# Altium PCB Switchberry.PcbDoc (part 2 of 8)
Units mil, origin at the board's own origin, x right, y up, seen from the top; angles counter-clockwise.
Board outline 4500 x 3824.8 mil, 6 copper layers (L01-TOP, L02-GND, L03-SIG, L04-SIG, L05-GND, L06-BOT), stack 49.214 mil thick; 431 components, 322 nets, 1699 pads, 1274 vias.
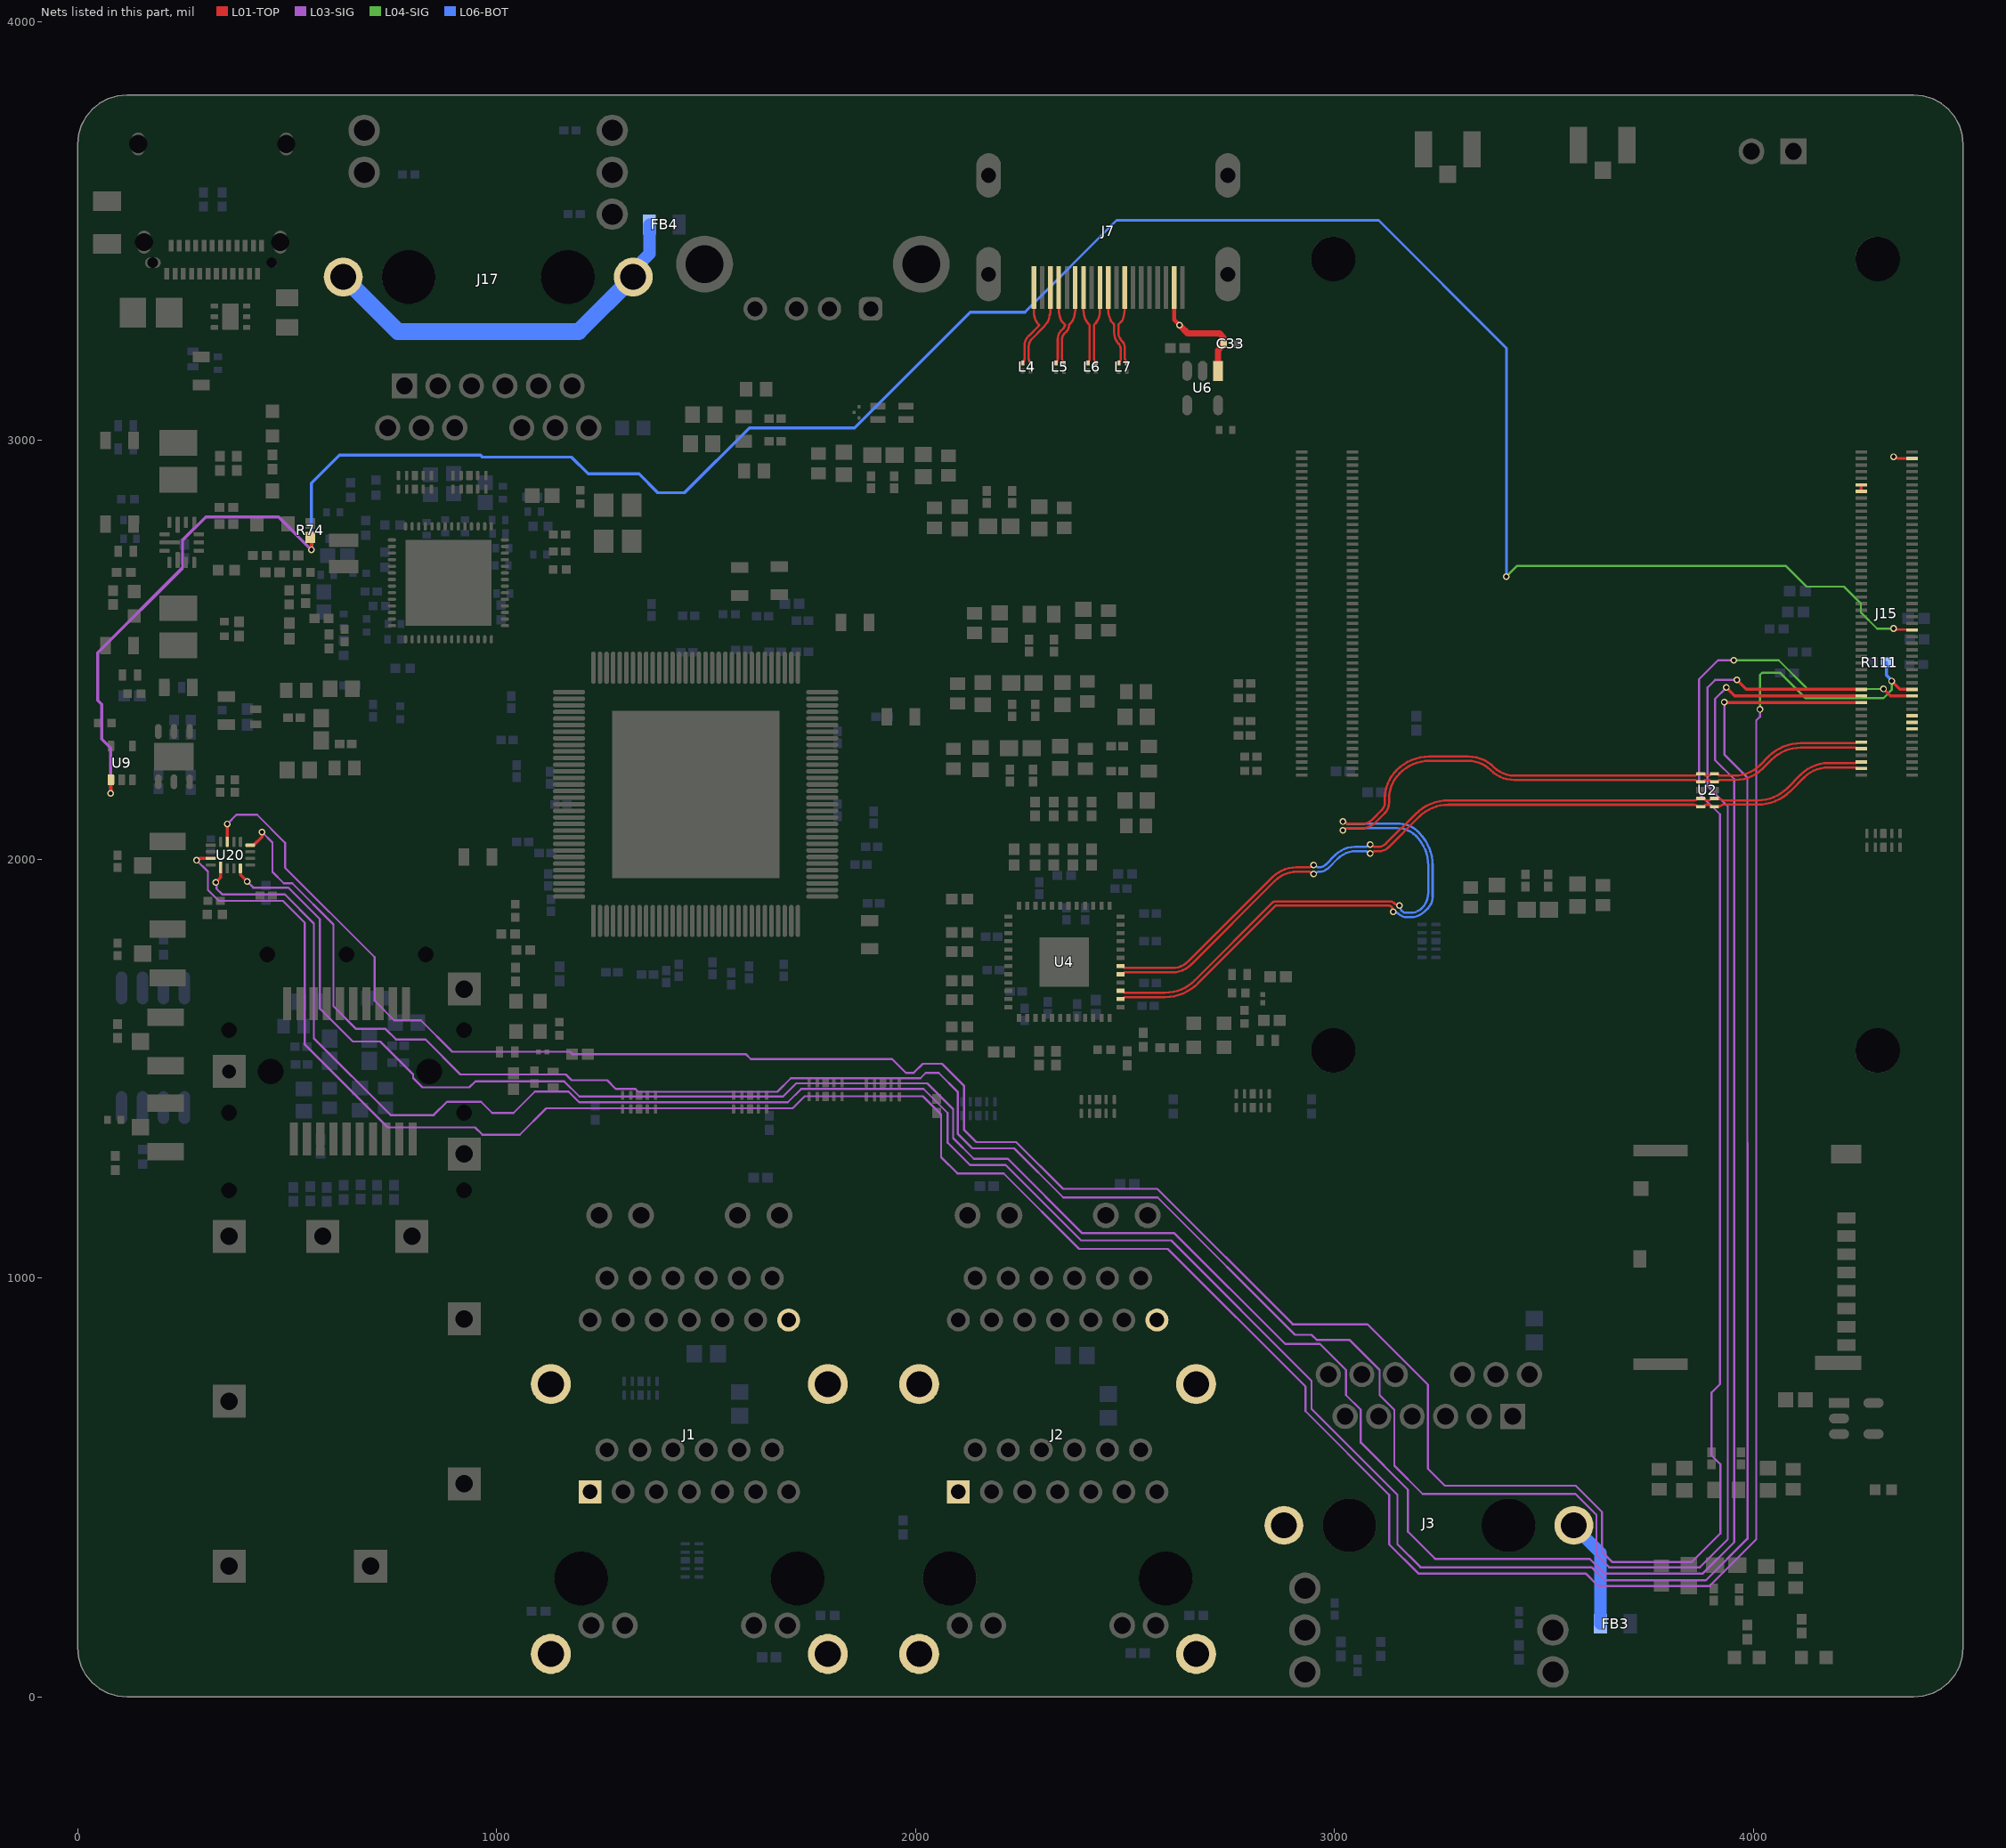
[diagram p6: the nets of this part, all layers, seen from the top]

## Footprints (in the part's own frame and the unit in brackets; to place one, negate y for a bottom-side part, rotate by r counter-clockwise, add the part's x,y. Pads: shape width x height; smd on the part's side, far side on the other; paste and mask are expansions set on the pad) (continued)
FP-CRCW0402-e3-IPC_B [mil]
  rect 22.37x22.54 smd paste+0 mask+0: 1(-17.8,0) 2(17.8,0)
  silkscreen extent -29,-27 29,27, body extent -35,-17 35,17, height 10
FP-CRCW0402-e3-IPC_C [mil]
  rect 18.43x18.6 smd paste+0 mask+0: 1(-15.83,0) 2(15.83,0)
  silkscreen extent -25,-27 25,27, body extent -20,-10 20,10, height 16
FP-DF40HC_3_0_-100DS-0_4V-MFG [mm]
  rect 0.2x0.7 smd paste-1000 mask+0: 1(-9.8,-1.54) 2(-9.8,1.54) 3(-9.4,-1.54) 4(-9.4,1.54) 5(-9,-1.54) 6(-9,1.54) 7(-8.6,-1.54) 8(-8.6,1.54) 9(-8.2,-1.54) 10(-8.2,1.54) 11(-7.8,-1.54) 12(-7.8,1.54) 13(-7.4,-1.54) 14(-7.4,1.54) 15(-7,-1.54) 16(-7,1.54) 17(-6.6,-1.54) 18(-6.6,1.54) 19(-6.2,-1.54) 20(-6.2,1.54) 21(-5.8,-1.54) 22(-5.8,1.54) 23(-5.4,-1.54) 24(-5.4,1.54) 25(-5,-1.54) 26(-5,1.54) 27(-4.6,-1.54) 28(-4.6,1.54) 29(-4.2,-1.54) 30(-4.2,1.54) 31(-3.8,-1.54) 32(-3.8,1.54) 33(-3.4,-1.54) 34(-3.4,1.54) 35(-3,-1.54) 36(-3,1.54) 37(-2.6,-1.54) 38(-2.6,1.54) 39(-2.2,-1.54) 40(-2.2,1.54) 41(-1.8,-1.54) 42(-1.8,1.54) 43(-1.4,-1.54) 44(-1.4,1.54) 45(-1,-1.54) 46(-1,1.54) 47(-0.6,-1.54) 48(-0.6,1.54) 49(-0.2,-1.54) 50(-0.2,1.54) 51(0.2,-1.54) 52(0.2,1.54) 53(0.6,-1.54) 54(0.6,1.54) 55(1,-1.54) 56(1,1.54) 57(1.4,-1.54) 58(1.4,1.54) 59(1.8,-1.54) 60(1.8,1.54) 61(2.2,-1.54) 62(2.2,1.54) 63(2.6,-1.54) 64(2.6,1.54) 65(3,-1.54) 66(3,1.54) 67(3.4,-1.54) 68(3.4,1.54) 69(3.8,-1.54) 70(3.8,1.54) 71(4.2,-1.54) 72(4.2,1.54) 73(4.6,-1.54) 74(4.6,1.54) 75(5,-1.54) 76(5,1.54) 77(5.4,-1.54) 78(5.4,1.54) 79(5.8,-1.54) 80(5.8,1.54) 81(6.2,-1.54) 82(6.2,1.54) 83(6.6,-1.54) 84(6.6,1.54) 85(7,-1.54) 86(7,1.54) 87(7.4,-1.54) 88(7.4,1.54) 89(7.8,-1.54) 90(7.8,1.54) 91(8.2,-1.54) 92(8.2,1.54) 93(8.6,-1.54) 94(8.6,1.54) 95(9,-1.54) 96(9,1.54) 97(9.4,-1.54) 98(9.4,1.54) 99(9.8,-1.54) 100(9.8,1.54)
  silkscreen extent -11.4,-2.62 11.4,1.57, body extent -11.5,-1.99 11.5,1.99, height 0.25
FP-DFE252012C-IPC_A [mil]
  rect 61.22x90.8 smd paste+0 mask+0: 1(-44.32,0) 2(44.32,0)
  silkscreen extent -75,-61 75,61, body extent -95,-65 95,65, height 10
FP-DLM0Q-MFG [mm]
  rect 0.3x0.23 smd paste+0 mask+0: 1(-0.25,0.24) 2(0.25,0.24) 3(0.25,-0.24) 4(-0.25,-0.24)
  silkscreen extent -1.1,-0.73 0.28,0.73, body extent -0.5,-0.46 0.5,0.46, height 0.25
FP-DLW21S-MFG [mm]
  rect 0.9x0.4 smd paste+0 mask+0: 1(-0.85,-0.4) 2(0.85,-0.4) 3(0.85,0.4) 4(-0.85,0.4)
  silkscreen extent -1.97,-1.01 1.11,1, body extent -1.4,-0.8 1.4,0.8, height 0.25
FP-DMX0003A-MFG [mm]
  rrect50% 0.2x0.2 smd paste-1000 mask-1000: 1(-0.15,0) 2(0.15,-0.34) 3(0.15,0.34)
  silkscreen extent -0.35,-0.87 0.35,0.87, body extent -0.45,-0.65 0.45,0.65, height 0.25
FP-DQA0010A-MFG [mm]
  rrect50% 0.565x0.2 smd paste+0 mask+0: 1(-0.417,1) 2(-0.417,0.5) 4(-0.417,-0.5) 5(-0.417,-1) 6(0.417,-1) 7(0.417,-0.5) 9(0.417,0.5) 10(0.417,1)
  rrect25% 0.565x0.4 smd paste-1000 mask+0: 3(-0.417,0) 8(0.417,0)
  silkscreen extent -1.37,-1.48 0.55,1.48, body extent -0.8,-1.4 0.8,1.4, height 0.25
FP-DRV0006A-MFG [mm]
  rrect33% 0.45x0.3 smd paste+0 mask+0: 1(-0.975,0.65) 2(-0.975,0) 3(-0.975,-0.65) 4(0.975,-0.65) 5(0.975,0) 6(0.975,0.65)
  rrect10% 1x1.6 smd paste-1000 mask+0: 7(0,0)
  silkscreen extent -1.88,-1.17 1.05,1.17, body extent -1.3,-1.15 1.3,1.15, height 0.25
FP-ECS-TXO-2520-MFG [mm]
  rect 0.9x0.8 smd paste+0 mask+0: 1(-0.925,-0.725) 2(0.925,-0.725) 3(0.925,0.725) 4(-0.925,0.725)
  silkscreen extent -1.05,-1.8 0.1,1.05, body extent -1.48,-1.22 1.48,1.22, height 0.25
FP-GRM15-MFG [mm]
  rect 0.4x0.5 smd paste+0 mask+0: 1(-0.4,0) 2(0.4,0)
  silkscreen extent -0.53,-0.63 0.53,0.63, body extent -0.3,-0.16 0.3,0.16, height 0.33
FP-GRM188-0_2-IPC_C [mil]
  rect 35.63x35.68 smd paste+0 mask+0: 1(-23.64,0) 2(23.64,0)
  silkscreen extent -41,-35 41,35, body extent -45,-24 45,24, height 10
FP-LTST-C190GKT-MFG [mm]
  rect 0.8x0.8 smd paste+0 mask+0: 1(-0.75,0) 2(0.75,0)
  silkscreen extent -1.92,-0.85 0.85,0.85, body extent -1.25,-0.55 1.25,0.55, height 0.25
FP-M20-9990246-MFG [mm]
  rect 1.57x1.57 hole 1.02 paste-2539.97 mask+0: 1(-1.27,0)
  round 1.57 hole 1.02 paste-2539.97 mask+0: 2(1.27,0)
  silkscreen extent -3.55,-1.32 2.79,1.32, body extent -2.89,-1.42 2.89,1.42, height 0.25
FP-RQR0014A-MFG [mm]
  rrect40% 0.625x0.25 smd paste+0 mask+0: 1(-1.038,0.5) 2(-1.038,0) 3(-1.038,-0.5) 8(1.038,-0.5) 10(1.038,0.5)
  rrect40% 0.25x0.675 smd paste+0 mask+0: 4(-0.75,-1.212) 5(-0.25,-1.212) 7(0.75,-1.212) 11(0.75,1.212) 13(-0.25,1.212) 14(-0.75,1.212)
  rrect40% 0.25x0.975 smd paste+0 mask+0: 6(0.25,-1.062) 12(0.25,1.062)
  rrect40% 1.225x0.25 smd paste+0 mask+0: 9(0.737,0)
  silkscreen extent -2.02,-1.55 1.35,1.55, body extent -1.45,-1.65 1.45,1.65, height 0.25
FP-RSV0016A-MFG [mm]
  rrect50% 0.7x0.2 smd paste+0 mask+0: 1(-0.75,0.6)
  rrect50% 0.6x0.2 smd paste+0 mask+0: 2(-0.8,0.2) 3(-0.8,-0.2) 4(-0.8,-0.6) 9(0.8,-0.6) 10(0.8,-0.2) 11(0.8,0.2) 12(0.8,0.6)
  rrect50% 0.2x0.6 smd paste+0 mask+0: 5(-0.6,-1.2) 6(-0.2,-1.2) 7(0.2,-1.2) 8(0.6,-1.2) 13(0.6,1.2) 14(0.2,1.2) 15(-0.2,1.2) 16(-0.6,1.2)
  silkscreen extent -1.9,-1.68 1.28,1.68, body extent -1.2,-1.6 1.2,1.6, height 0.25
FP-RT9742GGJ5-IPC_C [mil]
  rect 48.02x23.17 smd paste+0 mask+0: 1(-41.07,36.99)
  rrect100% 48.02x23.17 smd paste+0 mask+0: 2(-41.07,0) 3(-41.07,-36.99) 4(41.07,-36.99) 5(41.07,36.99)
  silkscreen extent -90,-57 3,57, body extent -69,-61 69,61, height 10
FP-SOT23_Standard-MFG [mm]
  rect 0.9x0.8 smd paste+0 mask+0: 1(-1,0.95) 2(-1,-0.95) 3(1,0)
  silkscreen extent -0.18,-1.5 0.7,1.5, body extent -1.55,-1.6 1.55,1.6, height 0.25
FP-U_FL-R-SMT-1_10-MFG [mm]
  rect 1x1.05 smd paste-1000 mask+0: 1(0,1.525)
  rect 1.05x2.2 smd paste-1000 mask+0: 2(-1.475,0) 3(1.475,0)
  silkscreen extent -0.58,-1.38 0.58,-1.38, body extent -2.1,-1.48 2.1,2.15, height 0.25
"I225 QFN56" [mm]
  oval 0.5x0.2 smd: 1(-3.425,2.6) 2(-3.425,2.2) 3(-3.425,1.8) 4(-3.425,1.4) 5(-3.425,1) 6(-3.425,0.6) 7(-3.425,0.2) 8(-3.425,-0.2) 9(-3.425,-0.6) 10(-3.425,-1) 11(-3.425,-1.4) 12(-3.425,-1.8) 13(-3.425,-2.2) 14(-3.425,-2.6) 29(3.425,-2.6) 30(3.425,-2.2) 31(3.425,-1.8) 32(3.425,-1.4) 33(3.425,-1) 34(3.425,-0.6) 35(3.425,-0.2) 36(3.425,0.2) 37(3.425,0.6) 38(3.425,1) 39(3.425,1.4) 40(3.425,1.8) 41(3.425,2.2) 42(3.425,2.6)
  oval 0.2x0.5 smd: 15(-2.6,-3.425) 16(-2.2,-3.425) 17(-1.8,-3.425) 18(-1.4,-3.425) 19(-1,-3.425) 20(-0.6,-3.425) 21(-0.2,-3.425) 22(0.2,-3.425) 23(0.6,-3.425) 24(1,-3.425) 25(1.4,-3.425) 26(1.8,-3.425) 27(2.2,-3.425) 28(2.6,-3.425) 43(2.6,3.425) 44(2.2,3.425) 45(1.8,3.425) 46(1.4,3.425) 47(1,3.425) 48(0.6,3.425) 49(0.2,3.425) 50(-0.2,3.425) 51(-0.6,3.425) 52(-1,3.425) 53(-1.4,3.425) 54(-1.8,3.425) 55(-2.2,3.425) 56(-2.6,3.425)
  rect 5.2x5.2 smd: PAD(0,0)
  silkscreen extent -4.42,-3.65 3.65,3.65, body extent -3.5,-3.5 3.5,3.5, height 0.9
MCHP-SOIC-S2A8_M [mm] "SOIC, 8-Leads, Body 5.275x5.275mm, Pitch 1.27mm, IPC Low Density"
  oval 2x0.7 smd: 1(-3.625,1.905) 2(-3.625,0.635) 3(-3.625,-0.635) 4(-3.625,-1.905) 5(3.625,-1.905) 6(3.625,-0.635) 7(3.625,0.635) 8(3.625,1.905)
  silkscreen extent -3.75,-2.7 2.23,2.93, body extent -2.7,-2.7 2.7,2.7, height 2.16
MICL-QFN-48_V [mm] "QFN, 48-Leads, Body 7.05x7.05mm, Pitch 0.5mm"
  rect 0.5x0.25 smd: 1(-3.4,2.75) 2(-3.4,2.25) 3(-3.4,1.75) 4(-3.4,1.25) 5(-3.4,0.75) 6(-3.4,0.25) 7(-3.4,-0.25) 8(-3.4,-0.75) 9(-3.4,-1.25) 10(-3.4,-1.75) 11(-3.4,-2.25) 12(-3.4,-2.75) 25(3.4,-2.75) 26(3.4,-2.25) 27(3.4,-1.75) 28(3.4,-1.25) 29(3.4,-0.75) 30(3.4,-0.25) 31(3.4,0.25) 32(3.4,0.75) 33(3.4,1.25) 34(3.4,1.75) 35(3.4,2.25) 36(3.4,2.75)
  rect 0.25x0.5 smd: 13(-2.75,-3.4) 14(-2.25,-3.4) 15(-1.75,-3.4) 16(-1.25,-3.4) 17(-0.75,-3.4) 18(-0.25,-3.4) 19(0.25,-3.4) 20(0.75,-3.4) 21(1.25,-3.4) 22(1.75,-3.4) 23(2.25,-3.4) 24(2.75,-3.4) 37(2.75,3.4) 38(2.25,3.4) 39(1.75,3.4) 40(1.25,3.4) 41(0.75,3.4) 42(0.25,3.4) 43(-0.25,3.4) 44(-0.75,3.4) 45(-1.25,3.4) 46(-1.75,3.4) 47(-2.25,3.4) 48(-2.75,3.4)
  rect 3x3 smd paste-4: 49(0,0)
  silkscreen extent -4.33,2.63 -4.08,2.87, body extent -3.5,-3.5 3.5,3.5, height 0.9
MOLX-74754-0101_V [mm] "SFP+ Cage, 1-Port, Body 49x15.9mm"
  rect 2x2 hole 1.05: MH1(-7.125,13.55) MH2(-7.125,3.55) MH3(-7.125,-6.45) MH4(-7.125,-16.45) MH6(7.125,-1.45) MH7(7.125,8.55) MH8(7.125,18.55) MH9(-1.455,18.55) MH10(-3.955,-1.45) MH11(1.445,-1.45)
  rect 2x2 hole 0.85: MH5(7.125,-11.45)
  round 0 hole 0.95: MH12(-7.13,-4.25) MH13(-7.13,-8.95) MH14(-7.13,-13.95) MH15(-4.8,-18.55) MH16(0,-18.55) MH17(4.8,-18.55) MH18(7.13,-13.95) MH19(7.13,-8.95) MH20(7.13,-4.25)
  L01-TOP keep-out region: 1,-19.25 1,-18.25 -1,-18.25 -1,-19.25
  L01-TOP keep-out region: -8.125,23.05 -8.125,-19.25 -3.795,-19.25 -3.795,-18.25 -6.125,-18.25 -6.125,-3.75 6.125,-3.75 6.125,-18.25 3.795,-18.25 3.795,-19.25 8.125,-19.25 8.125,23.05
  silkscreen extent -7.95,-18.95 7.95,23.06, body extent -7.95,-18.94 7.95,30.05, height 10.21
MOLX-503398-1892_V [mm] "CONN, 8-Leads, Body 14.05x13.2mm, Pitch 1.1mm"
  rect 0.7x1.1 smd: 1(-2.38,6.27) 2(-1.28,6.27) 3(-0.18,6.27) 4(0.92,6.27) 5(2.02,6.27) 6(3.12,6.27) 7(4.22,6.27) 8(5.32,6.27)
  rect 1.05x0.78 smd: 9(0.095,-6.27)
  rect 0.9x0.93 smd: 10(-4.17,-6.195)
  rect 0.86x2.8 smd: 11(6.4,5.77)
  rect 0.7x3.3 smd: 12(6.48,-5.01) 13(-6.48,-5.01)
  rect 1.14x1.83 smd: 14(-6.26,6.255)
  L01-TOP keep-out region: -6.832,-0.632 -6.132,-0.632 -6.132,1.768 -6.832,1.768
  L01-TOP keep-out region: -5.235,-6.08 -4.685,-6.08 -4.685,-3.93 -5.235,-3.93
  L01-TOP keep-out region: -3.218,-6.278 -2.668,-6.278 -2.668,-5.728 -3.218,-5.728
  L01-TOP keep-out region: 6.83,4.37 6.83,-3.36 6.13,-3.36 6.13,-5.88 -0.43,-5.88 -0.43,-6.66 -1.73,-6.66 -1.73,-4.48 0.57,-4.48 0.57,-3.23 -3.82,-3.23 -3.82,-0.63 -3.17,-0.63 -3.17,4.37
  silkscreen extent -6.6,-6.38 6.6,8.82, body extent -6.55,-6.38 6.55,7.67, height 1.28
RESC0402(1005)_L [mm] "Chip Resistor, Body 1.0x0.5mm, IPC High Density"
  rect 0.45x0.55 smd: 1(-0.45,0) 2(0.45,0)
  body extent -0.52,-0.27 0.53,0.28, height 0.4
RESC1005X40X25LL05T05 [mm] "Chip Resistor, 2-Leads, Body 1.00x0.50mm, IPC High Density"
  rect 0.45x0.45 smd: 1(-0.4,0) 2(0.4,0)
  body extent -0.53,-0.27 0.53,0.28, height 0.4
RESC1005X40X25LL10T10 [mm] "Chip Resistor, 2-Leads, Body 1.00x0.50mm, IPC High Density"
  rect 0.55x0.5 smd: 1(-0.375,0) 2(0.375,0)
  body extent -0.55,-0.3 0.55,0.3, height 0.4
RESC1005X40X25ML05T05 [mm] "Chip Resistor, 2-Leads, Body 1.00x0.50mm, IPC Low Density"
  rect 0.65x0.65 smd: 1(-0.5,0) 2(0.5,0)
  body extent -0.53,-0.27 0.53,0.28, height 0.4
RESC1005X40X25ML05T10 [mm] "Chip Resistor, 2-Leads, Body 1.00x0.50mm, IPC Low Density"
  rect 0.7x0.65 smd: 1(-0.475,0) 2(0.475,0)
  body extent -0.53,-0.27 0.53,0.28, height 0.4
RESC1005X40X25NL05T05 [mm] "Chip Resistor, 2-Leads, Body 1.00x0.50mm, IPC Medium Density"
  rect 0.55x0.55 smd: 1(-0.45,0) 2(0.45,0)
  body extent -0.53,-0.27 0.53,0.28, height 0.4
RESC1005X40X25NL05T10 [mm] "Chip Resistor, 2-Leads, Body 1.00x0.50mm, IPC Medium Density"
  rect 0.6x0.55 smd: 1(-0.425,0) 2(0.425,0)
  body extent -0.53,-0.27 0.53,0.28, height 0.4
RESC1005X40X25NL10T10 [mm] "Chip Resistor, 2-Leads, Body 1.00x0.50mm, IPC Medium Density"
  rect 0.65x0.6 smd: 1(-0.425,0) 2(0.425,0)
  body extent -0.55,-0.3 0.55,0.3, height 0.4
RESC1608X55X25ML10T15 [mm] "Chip Resistor, 2-Leads, Body 1.60x0.80mm, IPC Low Density"
  rect 0.8x1 smd: 1(-0.75,0) 2(0.75,0)
  body extent -0.85,-0.45 0.85,0.45, height 0.55
RESC2013X60X35NL10T20 [mm] "Chip Resistor, 2-Leads, Body 2.00x1.25mm, IPC Medium Density"
  rect 1x1.35 smd: 1(-0.9,0) 2(0.9,0)
  silkscreen extent -0.1,-0.58 0.1,0.58, body extent -1.05,-0.67 1.05,0.67, height 0.6
TDK-MPZ2012_V [mm] "SMD, 2-Leads, Body 2x1.25mm"
  rect 0.8x1.2 smd: 1(-0.9,0) 2(0.9,0)
  silkscreen extent -0.1,-0.63 0.1,0.63, body extent -1,-0.63 1,0.63, height 1.05
TECO-1367073-1_V [mm] "Connector, 20-Leads, Body 11.2x7.5mm, Pitch 0.8mm"
  rect 0.5x2 smd: 1(-3.2,-4.1) 2(-2.4,-4.1) 3(-1.6,-4.1) 4(-0.8,-4.1) 5(0,-4.1) 6(0.8,-4.1) 7(1.6,-4.1) 8(2.4,-4.1) 9(3.2,-4.1) 10(4,-4.1) 11(3.6,4.1) 12(2.8,4.1) 13(2,4.1) 14(1.2,4.1) 15(0.4,4.1) 16(-0.4,4.1) 17(-1.2,4.1) 18(-2,4.1) 19(-2.8,4.1) 20(-3.6,4.1)
  round 1.25 hole 1.55 unplated: MH1(-4.6,0) MH2(5,0)
  L01-TOP keep-out region: -5.55,-4.34 -3.79,-4.34 -3.79,-2.032 -5.55,-2.032
  L01-TOP keep-out region: 5.95,-2.286 4.59,-2.286 4.59,-4.34 5.95,-4.34
  L01-TOP keep-out region: 5.95,3.94 4.19,3.94 4.19,2.286 5.95,2.286
  L01-TOP keep-out region: 5.95,2.88 4.05,2.88 4.05,-2.88 5.95,-2.88
  L01-TOP keep-out region: -5.55,-2.88 -3.65,-2.88 -3.65,2.88 -5.55,2.88
  L01-TOP keep-out region: -5.55,2.032 -4.19,2.032 -4.19,3.94 -5.55,3.94
  silkscreen extent -3.32,-5.77 -3.08,-5.53, body extent -5.31,-4.49 5.69,4.51, height 5.2
"WE-TMSB 0201" [mm] "Chip Inductor, 2-Leads, Body 0.6x0.3mm, IPC Medium Density"
  rect 0.3x0.3 smd: 1(-0.25,0) 2(0.25,0)
  body extent -0.3,-0.15 0.3,0.15, height 0.28

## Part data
C1 C4 C7 C10 C63 C66 C70 C73 C78 C81 C90 C93 C98 C101 C106 C109 C119 C122 C134 C137 C149 C152 C157 C160 C165 C168: library part CMP-2006-02285-3, "CAP CER 10UF 6.3V X5R 0603", Capacitance=10uF, Manufacturer=Kemet, Manufacturer Part Number=C0603C106M9PACTU, Temperature="-55°C to +85°C", Temperature Characteristic=X5R, Temperature Coefficient=15%, Temperature Range High=+85°C, Temperature Range Low=-55°C, Tolerance=20%, Voltage Rating=6.3V
C2 C5 C8 C11 C64 C67 C71 C74 C79 C82 C91 C94 C99 C102 C107 C110 C120 C123 C135 C138 C150 C153 C158 C161 C166 C169: library part CMP-2006-03238-1, Manufacturer=Kemet, Part Number=C0603C475K8PACTU
C3 C6 C9 C12 C32 C65 C68 C69 C72 C75 C76 C77 C80 C83 C84 C85 C86 C87 C88 C89 C92 C95 C96 C97 C100 C103 C104 C105 C108 C111 C112 C113 C114 C115 C116 C117 C118 C121 C124 C125 C126 C127 C128 C129 C130 C131 C132 C133 C136 C139 C140 C141 C142 C143 C144 C145 C146 C147 C148 C151 C154 C155 C156 C159 C162 C163 C164 C167 C170 C171 C172 C173 C182 C184: library part CMP-2008-02519-2, "General Purpose Ceramic Capacitor, 0402, 100nF, 10%, X7R, 15%, 25V", Capacitance=100nF, Case Code (Imperial)=0402, Case Code (Metric)=1005, Dielectric=X7R, Max Operating Temperature=125°C, Min Operating Temperature=-55°C, Package Quantity=1, Tolerance=10%, Voltage=25V
C13 C17 C20 C23 C36 C42 C46 C47 C48 C49 C52 C56: library part CMP-13271-000002-1, "CAP CER 10UF 10V X5R 0402", Capacitance=10uF, Manufacturer=Samsung, Manufacturer Part Number=CL05A106MP5NUNC, Temperature="-55°C to +85°C", Temperature Characteristic=X5R, Temperature Coefficient=15%, Temperature Range High=+85°C, Temperature Range Low=-55°C, Tolerance=20%, Voltage Rating=10V
C14 C18 C21 C24 C53 C57: library part CMP-14477-000104-2, "None", Capacitance=1uF, Case Code (Imperial)=0402, Case Code (Metric)=1005, Dielectric=X5R, Max Operating Temperature=85°C, Min Operating Temperature=-55°C, Package Quantity=1, Tolerance=10%, Voltage Rating=16V
C15: library part CMP-06035-045466-1, "Chip Multilayer Ceramic Capacitors for General Purpose, 0603, 10uF, X5R, 15%, 20%, 35V", Capacitance=10uF, Case Code (Imperial)=0603, Case Code (Metric)=1608, Dielectric=X5R, Max Operating Temperature=85°C, Min Operating Temperature=-55°C, Tolerance=20%, Voltage Rating=35V
C16 C19 C22 C25 C37 C44 C54 C58 C60 C62 C174 C175: library part CMP-1034-02068-3, "CAP CER 0.1UF 16V 5% X7R 0402", Capacitance="0.10 μF", Manufacturer=Kemet, Manufacturer Part Number=C0402C104J4RACTU, Package=C0402-BB, Temperature="-55°C to +125°C", Temperature Characteristic=X7R, Temperature Coefficient=15%, Temperature Range High=+125°C, Temperature Range Low=-55°C, Tolerance=0.05, Voltage Rating="16 V"
C26 C27 C28 C29 C31: library part CMP-2100-03643-1, "Chip Capacitor, 0.1 uF, +/- 10%, 50 V, -55 to 125 degC, 0603 (1608 Metric), RoHS, Tape and Reel", Capacitance=100nF, Case Code (Imperial)=0603, Case Code (Metric)=1608, Dielectric=X7R, Dielectric Material=Ceramic, Insulation Resistance=10GR, Manufacturer=Murata, Max Operating Temperature=125degC, Min Operating Temperature=-55degC, Package Description="2-Pin Surface Mount Device, Body 1.6 x 0.8 mm", Package Quantity=1, Tolerance=10%, Voltage=50V
C30 C33 C34 C188 C190 C191 C192 C193 C194 C195 C196 C197 C198 C199 C200 C201 C202 C203 C204 C205 C206 C208: library part CMP-2100-03641-2, "CAP CER 0.1UF 16V X7R 0402", Capacitance=0.10μF, Manufacturer=Murata, Manufacturer Part Number=GRM155R71C104KA88D, Package=GRM15, Temperature="-55°C to +125°C", Temperature Characteristic=X7R, Temperature Range High=+125°C, Temperature Range Low=-55°C, Tolerance=10%, Voltage Rating=16Vdc
C35: library part CMP-2000-05396-3, "Multilayer Ceramic Capacitors 100uF ±20% 10V X5R SMD 1206", Capacitance=100uF, Case Code (Imperial)=1206, Case Code (Metric)=3216, Dielectric=X5R, Dielectric Material=Ceramic, Max Operating Temperature=85°C, Min Operating Temperature=-55°C, Package Quantity=1, Tolerance=20%, Voltage=10V
C38 C39 C43: library part CMP-2000-05997-2, "CAP CER 4.7UF 10V X5R 0402", Capacitance=4.7uF, Case Code (Imperial)=0402, Case Code (Metric)=1005, Dielectric=X5R, Dielectric Material=Ceramic, Max Operating Temperature=85°C, Min Operating Temperature=-55°C, Package Quantity=10000, Tolerance=10%, Voltage Rating=10V
C40 C41 C50 C51 C55 C59 C176 C177 C178 C179 C180 C181: library part CMP-2000-05441-1, "Chip Capacitor, 22 uF, +/- 20%, 10 V, -55 to 85 degC, 0603 (1608 Metric), RoHS, Tape and Reel", Capacitance=22µF, Manufacturer=TDK, Operating Temperature=-55degC~85degC, Package / Case=0603(1608Metric), Package Description="2-Pin Surface Mount Device, Body 1.6 x 0.8 mm", Package Reference=603, PCN Part Number=MLCCPartNumberChange30/Nov/2012, Ratings=-, Standard Package=1, Temperature Coefficient=X5R, Tolerance=±20%, Voltage - Rated=10V
C45: library part CMP-13271-001936-1, "Cap Ceramic 1uF 10V X5R ±10% SMD 0402 +85°C Paper T/R", Capacitance=1uF, Case Code (Imperial)=0402, Case Code (Metric)=1005, Dielectric=X5R, Max Operating Temperature=85°C, Min Operating Temperature=-55°C, Package Quantity=1, Tolerance=10%, Voltage Rating=10V
C61: library part CMP-2000-05436-2, "CAP CER 1000PF 2KV X7R 1206", Capacitance=1nF, Case Code (Imperial)=1206, Case Code (Metric)=3216, Dielectric=X7R, Insulation Resistance=10GR, Max Operating Temperature=125°C, Min Operating Temperature=-55°C, Package Quantity=1, Resistor Type=Ceramic, Tolerance=10%, Voltage=2kV
C186 C187: library part CMP-1034-00890-3, "CAP CER 20PF 50V 5% NP0 0402", Capacitance="20 pF", Manufacturer=Kemet, Manufacturer Part Number=C0402C200J5GACTU, Package=C0402-BB, Temperature="-55°C to +125°C", Temperature Characteristic=C0G, Temperature Coefficient=15%, Temperature Range High=+125°C, Temperature Range Low=-55°C, Tolerance=0.05, Voltage Rating="50 V"
C189: library part CMP-2006-03300-2, "CAP CER 0.1UF 50V X7R 0603", Capacitance=100nF, Manufacturer=Kemet, Manufacturer Part Number=C0603X104K5RACTU, Package=C0603-CJ, Temperature="-55°C to +125°C", Temperature Characteristic=X7R, Temperature Coefficient=15%, Temperature Range High=+125°C, Temperature Range Low=-55°C, Tolerance=10%, Voltage=50V
C207 C209 C210 C211 C212 C213: library part CMP-2000-06337-3, "Chip Multilayer Ceramic Capacitors for General Purpose, 0603, 22uF, X5R, 15%, 20%, 10V", Capacitance=22uF, Case Code (Imperial)=0603, Case Code (Metric)=1608, Dielectric=X5R, Max Operating Temperature=85°C, Min Operating Temperature=-55°C, Package Quantity=4000, Tolerance=20%, Voltage Rating=10V
D1 D2 D5 D6: library part CMP-22017-000005-2, "LED GREEN CLEAR CHIP SMD", Case Code (Imperial)=0603, Case Code (Metric)=1608, Color=Green, Forward Current=30mA, Forward Voltage=2.1V, Lens Color=Colorless, Max Operating Temperature=85°C, Min Operating Temperature=-55°C, Package Quantity=1, Power Dissipation=100mW, Reverse Voltage=5V, Test Current=10mA, Voltage=2V
D3: library part CMP-04989-000013-1, "TVS DIODE 3.6V 8.4V 3X2SON", Average Rectified Current=10A, Case/Package=TO-220-3, Clamping Voltage=8.4V, Max Operating Temperature=125°C, Max Reverse Voltage (DC)=100V, Min Breakdown Voltage=5.1V, Min Operating Temperature=-40°C, Peak Pulse Current=2.5A, Peak Pulse Power=20W, Power Line Protection=No, Resistor Type=Zener, Reverse Standoff Voltage=3.6V
D4: library part CMP-04989-000008-1, "UNIDIR PRECISION SURGE DIODE", Clamping Voltage=9.5V, Max Operating Temperature=125°C, Min Breakdown Voltage=7.5V, Min Operating Temperature=-40°C, Peak Pulse Current=43A, Peak Pulse Power=400W, Power Line Protection=No, Resistor Type=Zener, Reverse Standoff Voltage=5V
FB1 FB2 FB5 FB6 FB7 FB8 FB9 FB10 FB11: library part CMP-0686-00556-7, "Chip Ferrite Bead, 0603, 220Ω @ 100MHz, 0.05Ω, 25%, 2.2A", Case Code (Imperial)=0603, Case Code (Metric)=1608, Current Rating=2.2A, DC Resistance (DCR)=50mR, Inductor Type="FERRITE BEAD", Max Operating Temperature=125°C, Min Operating Temperature=-55°C, Package Quantity=1, Test Frequency=100MHz, Tolerance=25%
FB3 FB4: library part CMP-2000-05400-1, "Chip Bead for Power Line, 600 Ohm, +/- 25%, 2 A, -55 to 125 degC, 2-Pin SMD (0805), RoHS, Tape and Reel", Case Height=0.85mm, Case Length=2mm, Case Width=1.25mm, Manufacturer=TDK, Maximum DC Current=2A, Maximum DC Resistance=100mOhms, Operating Temperature Range=-55Cto+125C, Package / Case=0805(2012metric), Package Description="2-Pin Surface Mount Device, Body 2 x 1.25 mm", Package Reference=805, Test Frequency=100MHz, Tolerance=25%
J1 J2: library part CMP-16034-000001-1, "CONN MAGJACK 2PORT 1000 BASE-T", Manufacturer="Bel Fuse", Package=0, Temperature="0°C to +70°C", Temperature Range High=+70°C, Temperature Range Low=0°C
J3 J17: "MagJack 2.5GBASE-T", Package=None
J4: library part CMP-2000-05488-1, "Female Connector, Pitch 0.8 mm, 2 x 10 Position, Height 5.4 mm, -55 to 85 degC, RoHS, Tape and Reel", Manufacturer="TE Connectivity", Package Description="Female Connector, Pitch 0.8 mm, 2 x 10 Position, Height 5.4 mm", Standard Package=1
J5: library part CMP-1704-00003-3, "SFP+ Cage, Single Port, Height 10.85 mm, Tail Height 3.05 mm, -40 to 85 degC, RoHS, Tray", Package Quantity=1152
J6 J10 J11 J12 J13 J16: library part CMP-2000-05152-3, "CONN U.FL RCPT STR 50 OHM SMD", Dielectric Material=Polymer, Frequency=6GHz, Housing Color=Beige, Insulation Resistance=500MR, Max Operating Temperature=90°C, Min Operating Temperature=-40°C, Package Quantity=2500
J7: library part CMP-1502-00169-3, Color=Black, Contact Resistance=30mΩ, Current Rating=500mA, Insulation Resistance=10MΩ, Max Operating Temperature=85°C, Min Operating Temperature=-25°C, Voltage Rating=40V
J8: library part CMP-1502-03227-2, Color=White, Contact Resistance=20mΩ, Current Rating=1.5A, Flammability Rating="UL94 V-0", Insulation Resistance=1GΩ, Max Operating Temperature=105°C, Min Operating Temperature=-40°C, Operating Supply Voltage=30V
J9: library part CMP-02355-000003-1, "CONN RCP USB3.1 TYPEC 24P SMD RA"
J14 J15: library part CMP-11605-000071-1, "CONN RCPT 100POS SMD GOLD", Package Quantity=3000
J18: library part CMP-15831-000009-1, "CONN HEADER VERT 2POS 2.54MM", Current Rating=3A, Manufacturer=Harwin, Temperature="-40°C to +105°C", Temperature Range High=+105°C, Temperature Range Low=-40°C
L1 L2: library part CMP-1490-00001-1, "Tiny Multilayer Suppression  Bead  WE-TMSB, Z= 60 Ohm", Manufacturer="Wuerth Elektronik"
L3: library part CMP-2000-06163-2, "Common Mode Choke, 0805, 90Ω @ 100MHz, 0.41Ω, 25%, 280mA", Case Code (Imperial)=0805, Current=280mA, DC Resistance (DCR)=410mR, Max Operating Temperature=85°C, Min Operating Temperature=-40°C, Package Quantity=1, Resistor Type=Wirewound, Test Frequency=100MHz, Tolerance=25%
L4 L5 L6 L7: library part CMP-06045-000424-1, "Chip Common Mode Choke Coil Monolithic 025020 50mA 90Ohm @ 100MHz"
L8 L9: library part CMP-06042-015149-1, "Shielded Wirewound Inductor 0.47uH 20% 4000mA 0.027Ω 1008 (2520)"
L10: library part CMP-13278-000005-1, "FIXED IND 1UH 4.1A 43 MOHM SMD", Case Code (Imperial)=0806, Case Code (Metric)=2016, Current Rating=4.1A, DC Resistance (DCR)=43mR, Inductance=1uH, Max Operating Temperature=125°C, Min Operating Temperature=-40°C, Resistor Type="Thin Film", Saturation Current=4.5A, Test Frequency=1MHz, Tolerance=20%
Q1: library part CMP-2000-04930-2, Case/Package=SOT-23, Continuous Drain Current (ID)=200mA, Current=2A, Drain to Source Breakdown Voltage=50V, Drain to Source Resistance=1.4Ω, Gate to Source Voltage (Vgs)=20V, Input Capacitance=50pF, Max Junction Temperature (Tj)=150°C, Max Power Dissipation=300mW, Min Operating Temperature=-55°C, Resistance=3.5Ω, Threshold Voltage=1.2V
R1 R2 R3 R4 R5 R6 R7 R8 R9 R73: library part CMP-2002-05217-1, Manufacturer=Bourns, Part Number=CR0402-FX-4701GLF
R10 R11 R12 R13 R41 R50 R52 R55 R56 R57 R58 R59 R60 R69 R71 R72 R74 R80 R82 R85 R90 R97 R98 R99 R100 R101 R102 R103 R111 R119: library part CMP-2002-04694-1, Manufacturer=Bourns, Part Number=CR0402-FX-1002GLF
R14 R15 R16 R17 R18 R19 R20 R21 R22 R23 R24 R25 R83 R84 R86 R87: library part CMP-2002-07182-1, Manufacturer="Yageo / Phycomp", Part Number=RC0402FR-1322RL
R26 R27 R70 R77: library part CMP-2002-05853-1, Manufacturer=Panasonic, Part Number=ERA-2AED331X
R28: library part CMP-2002-00433-1, Manufacturer=Panasonic, Part Number=ERJ-2GEJ103X
R29 R30 R43 R44 R45 R46 R47 R48 R49 R62 R63 R64 R67 R75 R78 R79 R81 R104 R105 R106 R107: library part CMP-2002-06457-1, Manufacturer=Panasonic, Part Number=ERJ-U020R00X
R31 R32 R33 R34 R35 R36 R37 R38 R39 R40 R95 R96: library part CMP-2002-07959-1, Manufacturer="Yageo / Phycomp", Part Number=RC0402JR-07220RL
R42: library part CMP-2002-04891-1, Manufacturer=Bourns, Part Number=CR0402-FX-1910GLF
R51: library part CMP-2002-06319-1, Manufacturer=Multicomp, Part Number=MC00625W040216K04
R53 R54 R108 R146 R150 R151: library part CMP-2002-03891-1, Manufacturer="KOA Speer", Part Number=RK73H1ETTP2200F
R61: library part CMP-1011-00697-1, "45K3 0.063W 1% 0402 (1005 Metric)  SMD", Case-EIA=0402, Case-Metric=1005, Power="0.063 W", Tolerance="1 %"
R65 R66: library part CMP-2002-07753-1, Manufacturer="Yageo / Phycomp", Part Number=RC0402FR-075K1L
R68: library part CMP-2002-00253-3, "Chip Resistor, 8.06 KOhm, +/- 1%, 63 mW, -55 to 155 degC, 0402 (1005 Metric), RoHS, Tape and Reel", Case Code (Imperial)=0402, Case Code (Metric)=1005, Manufacturer="Basic Passives", Max Operating Temperature="155 degC", Min Operating Temperature="-55 degC", Package Quantity=10000, PartNumber=CRCW04028K06FKED, Power Rating="63 mW", Resistance="8.06 KOhm", Tolerance=1%, Voltage Rating="50 V"
R76: library part CMP-2001-04478-1, Manufacturer=Yageo, Part Number=AC0805FR-070RL
R88: library part CMP-2002-06478-1, Manufacturer=Multicomp, Part Number=MCMR04X1001FTL
R89: library part CMP-2002-05926-1, Manufacturer=Multicomp, Part Number=MC00625W0402112K1
R91 R92 R93 R94: library part CMP-2100-03667-1, "Chip Resistor, 0 Ohm, +/- 5%, 0.1 W, -55 to 155 degC, 0603 (1608 Metric), RoHS, Tape and Reel", Case Code (Imperial)=0603, Case Code (Metric)=1608, Manufacturer=Yageo, Max Operating Temperature=155degC, Min Operating Temperature=-55degC, Package Description="2-Pin Surface Mount Device, Body 1.6 x 0.8 mm", Package Quantity=5000, Power Rating=100mW, Resistance=0mOhm, Temperature Coefficient=200ppm/degreesC, Tolerance=5%, Voltage Rating=50V
R109 R110: library part CMP-2002-00965-1, Manufacturer=Panasonic, Part Number=ERJ-2RKF4990X
R112 R113 R115 R116 R117 R118 R121 R122 R124 R125 R126 R129 R131 R132 R133 R138 R140: library part CMP-2002-04569-1, Manufacturer="KOA Speer", Part Number=RK73Z1ETTP
R130 R136 R137 R139 R141 R142 R143 R144 R145 R147 R148 R149: library part CMP-2002-08136-3, "RES Thick Film, 10kΩ, 5%, 0.063W, 200ppm/°C, 0402", Case Code (Imperial)=0402, Case Code (Metric)=1005, Max Operating Temperature=155°C, Max Power Dissipation=63mW, Min Operating Temperature=-55°C, Package Quantity=1, Resistance=10kR, Temperature Coefficient=200ppm/°C, Tolerance=5%, Voltage Rating=50V
R134: library part CMP-1011-00659-2, Manufacturer="Vishay Dale", Part Number=CRCW040222K0FKED
R135: library part CMP-1011-00429-3, "RES Thick Film, 200Ω, 1%, 0.063W, 100ppm/°C, 0402", Case Code (Imperial)=0402, Case Code (Metric)=1005, Max Operating Temperature=155°C, Max Power Dissipation=63mW, Min Operating Temperature=-55°C, Package Quantity=10, Resistance=200R, Temperature Coefficient=100ppm/°C, Tolerance=1%, Voltage Rating=50V
SD1: library part CMP-2000-05621-1, "Micro SD Connector, Pitch 1.1 mm, 8 Position, Height 1.4 mm, -25 to 85 degC, RoHS, Tape and Reel", Current Rating=500mA, Manufacturer=Molex, Package Description="Micro SD Connector, Pitch 1.1 mm, 8 Position, Height 1.4 mm", Voltage Rating=10VAC/DC
U1: library part CMP-06281-000207-1, "IC ETHERNET SWITCH 7PORT 128TQFP", Max Operating Temperature=85°C, Min Operating Temperature=-40°C
U2 U5 U10 U11 U12 U13 U14 U15 U16 U17 U19 U21: library part CMP-04985-000004-1, "TVS DIODE 5.5V 14V 10USON", Ambient Temperature Range High=+125°C, Ambient Temperature Range Low=-40°C, Breakdown Voltage=6.4V, Capacitance=0.5pF, Clamping Voltage=14V, Manufacturer="Texas Instruments", Operating Supply Voltage=5.5V, Package=DQA0010A, Peak Pulse Current=2.5A, Peak Pulse Power=2.5W, Temperature="-40°C to +125°C"
U3 U6: library part CMP-79883-000001-1, "IC PWR SWTCH N-CHAN 1:1 TSOT23-5", Case/Package=SOT-23-5, Max Operating Temperature=85°C, Max Output Current=1A, Min Operating Temperature=-40°C, On-State Resistance=70mR
U4: library part CMP-1337-00003-2, "Gigabit Ethernet Transceiver with RGMII Support, 1.14 to 1.26 V, 0 to 70 degC, 48-Pin QFN, RoHS", Manufacturer=Micrel, Temperature Range="0 to 70 degC"
U7: library part CMP-04918-000654-1, "Adjustable-Frequency Dual Step-Down Converter, 2.7-6V VIN, 0.6-5.5V 2A VOUT, VQFN-HR14"
U8: library part CMP-0244-00287-1, "1 A Low Quiescent Current Low Noise Voltage Regulator, Adjustable from 0.8V, 6-Pin VFDFPN, Tape and Reel"
U9: library part CMP-0859-00286-3, "Automotive Catalog Low-Power Single 2-Input Positive-AND Gate, DCK0005A, LARGE T&R", F @ Nom Voltage(Max)(Mhz)=100, Generic Part Number=SN74AUP1G08-Q1, ICC @ Nom Voltage(Max)(mA)=0.0009, Manufacturer="Texas Instruments", Operating Temperature Range(C)="-40 to 125", Rating=Automotive, tpd @ Nom Voltage(Max)(ns)=32.8,20.9,14.2,11,7.6,6.2, Voltage(Nom)(V)=0.8,1.2,1.5,1.8,2.5,3.3
U20: library part CMP-04892-000064-2, "IC SWITCH SPDT QUAD 16UQFN"
U22: library part CMP-0378-00041-1, "16 Mbit SPI Serial Flash, 2.7 to 3.6 V, 50 MHz, 0 to 70 degC, 8-pin SOIC (S2A8), Tube", Manufacturer=Microchip
U23 U24: library part CMP-0326-00027-3, "ESD Solution for Super-Speed (6 GBPS) USB 3.0 Interface, 4 Channels, -40 to +85 degC, 10-pin SON (DQA), Green (RoHS & no Sb/Br)", Breakdown Voltage(Min)(V)=8, Differential Capacitance(pF)=0.05, IO Capacitance(Typ)(pF)=0.8, IO Leakage Current(nA)=10, Manufacturer="Texas Instruments"
Y1 Y2: library part CMP-40224-000034-1, "XTAL OSC TCXO 25.0000MHZ HCMOS"
Y3: library part CMP-2000-05733-2, "CRYSTAL 25.0000MHZ 18PF SMD", Frequency=25MHz, Load Capacitance=18pF, Manufacturer=Abracon, Package=ABM8G, Temperature="-40°C to +85°C", Temperature Range High=+85°C, Temperature Range Low=-40°C, Tolerance=20ppm

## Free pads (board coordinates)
  round 106.3 hole 106.3: 1(2996.79,1543.44) 1(2996.79,3433.21) 1(4296.01,3433.21) 1(4296.15,1543.44)

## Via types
v1: diameter 16, hole 10, L01-TOP to L06-BOT, tented both sides, 1262 vias
v2: diameter 11.81, hole 7.87, L01-TOP to L06-BOT, tented both sides, 4 vias
v3: diameter 19.68, hole 7.87, L01-TOP to L06-BOT, tented both sides, 4 vias
v4: diameter 157.48, hole 110.24, L01-TOP to L06-BOT, tented both sides, 4 vias

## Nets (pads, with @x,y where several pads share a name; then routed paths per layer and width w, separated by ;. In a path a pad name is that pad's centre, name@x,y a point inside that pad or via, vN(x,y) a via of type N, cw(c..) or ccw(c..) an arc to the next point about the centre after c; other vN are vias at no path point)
1V8: J15.88 J15.90 | length 15.7
  L01-TOP w8: J15.88@4256.64,2878.09 J15.90@4256.64,2893.83
5V_HDMI: C33.2 J7.18 U6.1 | length 297.3
  L01-TOP w10: J7.18@2617.17,3365 2617.17,3287.83 v1(2630,3275)
  L01-TOP w15: v1@2630.19,3274.81 2650,3255 2725.84,3255 2734.63,3246.21 2734.63,3230.37 C33.2@2735,3230 2735,3228.03 2721.99,3215.02 U6.1@2721.99,3166.07
BRD_RST_N: J15.45 R74.2 U9.1 | length 6196.9
  L01-TOP w6: v1(4334,2551) 4336.69,2548.31 4376.96,2548.31 J15.45@4377.9,2547.38
  L01-TOP w7.27: v1(78.93,2157.41) 79.41,2157.89 U9.1@79.41,2189.65 ; R74.2@555,2768.27 557.72,2765.55 v1(557.72,2738.88)
  L03-SIG w7.27: v1(78.93,2157.41) 78.93,2265.91 57.76,2287.09 57.76,2369.79 48.36,2379.18 48.36,2493.37 250.44,2695.44 250.44,2761.51 305.72,2816.79 479.81,2816.79 v1(557.72,2738.88)
  L04-SIG w4.97: v1(3410,2675) 3435,2700 4077.43,2700 4126.43,2651 4215.54,2651 4256.17,2610.37 4256.17,2589.18 4294.84,2550.51 4333.51,2550.51 v1(4334,2551)
  L06-BOT w6: 2260.72,3305.94 2479.78,3525 3105,3525 3410,3220 v1(3410,2675)
  L06-BOT w7.27: v1(557.72,2738.88) 557.72,2897.72 624.95,2964.95 961.38,2964.95 966.33,2960 1178.53,2960 1218.53,2920 1340,2920 1385,2875 1448.38,2875 1603.38,3030 1854.6,3030 2130.54,3305.94 2260.72,3305.94
CHASSIS_CM4_GND: FB4.2 J17.S1 J17.S2 | length 940.7
  L06-BOT w30: J17.S2@1326,3390 1326,3406.97 1364.57,3445.54 FB4.2@1364.57,3515
  L06-BOT w40: J17.S1@634,3390 764,3260 1196,3260 J17.S2@1326,3390
CHASSIS_GND: FB3.2 J1.1 J1.20 J1.35 J1.36 J1.37 J1.38 J2.1 J2.20 J2.35 J2.36 J2.37 J2.38 J3.S1 J3.S2 | length 261.3
  L06-BOT w30: J3.S1@3571,410 3571,407.93 3634.57,344.37 FB3.2@3634.57,175
CM4_GPIO13: J15.28 U20.8 | length 7157.4
  L01-TOP w7.27: U20.8@412.24,2033.62 420.12,2033.62 440,2053.5 v1(440,2065) ; v1(3960,2428.37) 3982.72,2405.65 J15.28@4256.64,2405.65
  L03-SIG w4.97: v1(440,2065) 465,2040 465,1970 492.2,1942.8 512.2,1942.8 610.49,1844.51 610.49,1649.51 665,1595 735,1595 760,1570 830,1570 913.67,1486.33 1165.34,1486.33 1179.13,1472.54 1263.84,1472.54 1284.88,1451.5 1331.6,1451.5 1338.01,1445.09 1670.09,1445.09 1702.44,1477.44 2011.53,1477.44 2024.12,1490.03 2054.97,1490.03 2101.01,1443.99 2101.01,1343.99 2135,1310 2235,1310 2352.46,1192.54 2577.64,1192.54 2905.27,864.9 2945,864.9 2956.97,852.94 3035.24,852.94 3107.4,780.78 3107.4,720.78 3142.6,685.58 3142.6,552.4 3210,485 3575,485 3625,435 3625,340 3655,310 3871.83,310 3938.36,376.53 3938.36,2126.55 3890,2174.91 3890,2410 3908.36,2428.37 v1(3960,2428.37)
CM4_GPIO19: J15.26 U20.4 | length 7050.6
  L01-TOP w7.27: U20.4@388.62,1978.5 388.62,1962.86 v1(404.62,1946.87) ; v1(3935,2410) 3955.1,2389.9 J15.26@4256.64,2389.9
  L03-SIG w4.97: v1(404.62,1946.87) 419.03,1932.45 502.55,1932.45 577.99,1857.01 577.99,1643.78 656.85,1564.93 721.97,1564.93 800.83,1486.07 800.83,1477.73 823.09,1455.47 934.84,1455.47 949.36,1470 1161.14,1470 1197.41,1433.73 1683.73,1433.73 1715,1465 2027.97,1465 2089.69,1403.28 2089.69,1334.31 2139,1285 2220,1285 2397.74,1107.26 2617.74,1107.26 2882.03,842.97 2965.21,842.97 3027.4,780.78 3027.4,720.78 3062.6,685.58 3062.6,607.4 3175,495 3175,395 3240,330 3608.82,330 3643.7,295.12 3878.98,295.12 3953.78,369.93 3953.78,2191.22 3907.76,2237.24 3907.76,2382.76 v1(3935,2410)
CM4_GPIO20: J15.27 R111.1 U20.15 | length 7501.7
  L01-TOP w7.27: v1(284.05,1997.57) 286.41,1997.57 290.96,2002.13 U20.15@317.76,2002.13 ; v1(4329.49,2425.51) 4349.35,2405.65 J15.27@4377.9,2405.65
  L03-SIG w4.97: v1(284.05,1997.57) 310.86,1970.77 310.86,1926.96 337.15,1900.67 489.88,1900.67 542.3,1848.25 542.3,1557.7 740,1360 948.44,1360 966.18,1342.25 1055.38,1342.25 1118.7,1405.57 1706.43,1405.57 1735.1,1434.24 2017.33,1434.24 2060.99,1390.58 2060.99,1289.01 2100,1250 2210,1250 2390,1070 2601.9,1070 2930.49,741.41 2930.49,682.55 3130,483.03 3130,365 3200,295 3599.25,295 3629.25,265 3895,265 4006.4,376.4 4006.4,2331.4 4015,2340 v1(4015,2357.82)
  L04-SIG w4.97: v1(4015,2357.82) 4015,2440 4020,2445 4063.73,2445 4124.34,2384.39 4309.65,2384.39 4329.49,2404.22 v1(4329.49,2425.51)
  L06-BOT w7.27: R111.1@4316.73,2470 4316.73,2439.49 4329.49,2426.74 v1(4329.49,2425.51)
CM4_GPIO21: J15.25 U20.11 | length 7369.7
  L01-TOP w7.27: U20.11@357.13,2041.5 357.13,2084.19 v1(357.41,2084.47) ; v1(4310,2406.63) 4326.74,2389.9 J15.25@4377.9,2389.9
  L03-SIG w4.97: v1(357.41,2084.47) 379.24,2106.31 428.29,2106.31 495,2039.59 495,1980 708.74,1766.26 708.74,1662.56 755.78,1615.52 819.48,1615.52 894.51,1540.49 1175.45,1540.49 1180.94,1535 1594.68,1535 1606.72,1522.96 1944.05,1522.96 1976.98,1490.03 1995.28,1490.03 2017.2,1511.94 2063.06,1511.94 2115.28,1459.72 2115.28,1354.72 2145,1325 2240,1325 2351.81,1213.19 2576.81,1213.19 2900,890 3078.18,890 3222.6,745.58 3222.6,545.13 3263.11,504.62 3575.38,504.62 3638.39,441.61 3638.39,346.61 3662.27,322.73 3852.73,322.73 3920.75,390.75 3920.75,555.91 3899.53,577.13 3899.53,726.88 3919.6,746.95 3919.6,2107.29 3869.76,2157.13 3869.76,2429.76 3915,2475 v1(3952.5,2475)
  L04-SIG w4.97: v1(3952.5,2475) 4060.15,2475 4128.52,2406.63 v1(4310,2406.63)
CM4_GPIO26: J15.24 U20.1 | length 7187.1
  L01-TOP w7.27: v1(330,1945) 341.38,1956.38 U20.1@341.38,1980.47 ; v1(3930,2375) 3930.55,2374.45 4256.34,2374.45 J15.24@4256.64,2374.15
  L03-SIG w4.97: v1(330,1945) 331.86,1943.14 331.86,1929.54 344.98,1916.42 494.12,1916.42 563.86,1846.68 563.86,1572.71 747.05,1389.51 849.82,1389.51 881.54,1421.23 962.77,1421.23 989.49,1394.51 1040.41,1394.51 1091.39,1445.49 1171.55,1445.49 1197.04,1420 1695,1420 1727.01,1452.01 2019.1,1452.01 2076.44,1394.66 2076.44,1323.56 2130,1270 2215,1270 2395,1090 2610,1090 2945,755 2945,687.91 3150,482.91 3150,365 3205,310 3613.41,310 3644.45,278.96 3886.23,278.96 3985.28,378.01 3985.28,591.53 3985.49,591.74 3985.49,1322.04 3985,1322.52 3985,2195 3930,2250 v1(3930,2375)
CM_GPIOx: J15.97 | length 45.7
  L01-TOP w6: v1(4334,2961.08) 4338.87,2961.08 4343.12,2956.83 J15.97@4377.9,2956.83
CON_HDMI0_CLK_N: J7.12 L7.1 | length 189.9
  L01-TOP w5.38: 2492.34,3237.34 cw(c2511.76,3256.76) 2484.29,3256.76 2484.3,3276.7 2490.49,3282.83 ccw(c2479.45,3293.98) 2494.51,3289.58 2497.03,3298.18 ccw(c2448.66,3312.33) 2499.06,3312.33 J7.12@2499.06,3365 ; 2492.37,3237.31 cw(c2474.83,3219.76) 2499.64,3219.76 2499.64,3194.97 ccw(c2510.86,3194.97) 2502.92,3187.04 cw(c2500.57,3184.69) L7.1@2503.9,3184.69
CON_HDMI0_CLK_P: J7.10 L7.4 | length 189.5
  L01-TOP w5.38: J7.10@2459.69,3365 2459.69,3311.06 ccw(c2508.28,3311.06) 2462.55,3294.62 2464.69,3288.67 ccw(c2479.45,3293.98) 2467.7,3283.58 2471.89,3278.85 ccw(c2508.28,3311.06) 2473.92,3276.7 2473.92,3256.71 ccw(c2511.64,3256.71) 2484.97,3230.03 ; L7.4@2485,3184.69 cw(c2488.33,3184.69) 2485.97,3187.04 ccw(c2478.04,3194.97) 2489.26,3194.97 2489.26,3219.72 ccw(c2474.72,3219.72) 2485,3230
CON_HDMI0_TX0_N: J7.9 L6.1 | length 185
  L01-TOP w5.38: L6.1@2430,3185 ccw(c2426.67,3185) 2429.03,3187.35 cw(c2436.96,3195.28) 2425.74,3195.28 2425.74,3275 ccw(c2391.31,3309.43) 2440,3309.43 J7.9@2440,3365
CON_HDMI0_TX0_P: J7.7 L6.4 | length 185.1
  L01-TOP w5.38: J7.7@2400.63,3365 2400.63,3310.57 ccw(c2450.93,3310.57) 2404.78,3290.57 2406,3287.74 ccw(c2420.4,3293.98) 2407.33,3285.3 2409.03,3282.74 ccw(c2450.93,3310.57) 2415.36,3275 2415.36,3195.28 cw(c2404.14,3195.28) 2412.08,3187.35 ccw(c2414.43,3185) L6.4@2411.1,3185
CON_HDMI0_TX1_N: J7.6 L5.1 | length 190.7
  L01-TOP w5.38: L5.1@2353.9,3184.69 ccw(c2350.57,3184.69) 2352.92,3187.04 cw(c2360.86,3194.97) 2349.64,3194.97 2349.64,3242.05 cw(c2367.95,3242.05) 2355,3255 2360.13,3260.13 ccw(c2344.1,3276.17) 2366.78,3276.17 ccw(c2332.57,3310.38) 2370.21,3279.99 2373.55,3284.13 ccw(c2361.34,3293.98) 2376.04,3288.5 2377.9,3293.48 ccw(c2332.57,3310.38) 2380.94,3310.38 J7.6@2380.94,3365
CON_HDMI0_TX1_P: J7.4 L5.4 | length 191
  L01-TOP w5.38: L5.4@2335,3184.69 cw(c2338.33,3184.69) 2335.97,3187.04 ccw(c2328.04,3194.97) 2339.26,3194.97 2339.26,3242.08 cw(c2367.88,3242.08) 2347.64,3262.32 2352.75,3267.43 ccw(c2343.95,3276.23) 2356.4,3276.23 cw(c2392.19,3312.02) 2354.89,3277.8 2349.78,3283.38 cw(c2361.34,3293.98) 2346.43,3289.11 2344.08,3296.29 cw(c2392.19,3312.02) 2341.57,3312.02 J7.4@2341.57,3365
CON_HDMI0_TX2_N: J7.3 L4.1 | length 176.2
  L01-TOP w5.38: L4.1@2274.33,3185.01 ccw(c2271,3185.01) 2273.36,3187.36 cw(c2281.29,3195.29) 2270.07,3195.29 2270.07,3225 cw(c2294.39,3225) 2277.19,3242.19 2302.5,3267.5 ccw(c2255.69,3314.31) 2306.62,3272.02 2314.21,3281.17 ccw(c2302.14,3291.19) 2317.42,3287.6 2320.13,3299.17 ccw(c2255.69,3314.31) 2321.89,3314.31 J7.3@2321.89,3342.08
CON_HDMI0_TX2_P: J7.1 L4.4 | length 174.3
  L01-TOP w5.38: L4.4@2255.43,3185.01 cw(c2258.76,3185.01) 2256.41,3187.36 ccw(c2248.48,3195.29) 2259.69,3195.29 2259.69,3225.05 cw(c2294.27,3225.05) 2269.82,3249.5 2295.16,3274.84 cw(c2325.68,3305.36) 2288.99,3282.62 2288.81,3282.92 cw(c2302.14,3291.19) 2288.6,3283.27 2288.42,3283.57 cw(c2325.68,3305.36) 2282.52,3305.36 J7.1@2282.52,3341.6
ETH_LED1: J15.19
ETH_LED2: J15.17
ETH_LED3: J15.15
ETH_PAIR0_N: J15.10 U2.2 U2.9 U4.3 | length 2558.5
  L01-TOP w5.38: U4.3@2488.86,1686.1 2490.49,1686.1 cw(c2490.49,1678.16) 2496.11,1683.78 ccw(c2501.72,1689.39) 2501.72,1681.45 2595.27,1681.45 ccw(c2595.27,1781.45) 2665.98,1710.74 2851.79,1896.54 cw(c2859.13,1889.2) 2859.13,1899.58 3132.16,1899.58 cw(c3132.16,1886.44) 3141.46,1895.73 3142.65,1894.54 ccw(c3149.06,1900.95) 3149.06,1891.88 3149.94,1891.88 cw(c3149.94,1884.94) v1(3154.85,1889.85) ; v1(3020,2069) ccw(c3020,2075.94) 3024.91,2071.03 3025.53,2071.66 cw(c3031.94,2065.24) 3031.94,2074.31 3065.11,2074.31 ccw(c3065.11,2119.89) 3097.34,2087.66 3119.62,2109.95 ccw(c3094.57,2135) 3130,2135 3130,2144.64 cw(c3215.36,2144.64) 3155,2205 3155.71,2205.71 cw(c3226.42,2135) 3226.42,2235 3318.73,2235 cw(c3318.73,2158.73) 3372.66,2212.66 ccw(c3428.97,2268.97) 3428.97,2189.34 3857.52,2189.34 cw(c3857.52,2178.58) 3865.13,2186.19 3865.13,2185.93 3865.75,2185.31 ccw(c3867.26,2186.82) 3867.26,2184.69 U2.2@3873.56,2184.69 3878.98,2184.69 ccw(c3878.98,2188.95) 3882,2185.93 3882,2186.19 3883.57,2187.76 cw(c3887.37,2183.96) 3887.37,2189.34 3890.4,2189.34 cw(c3890.4,2178.58) 3898,2186.19 3898,2185.93 3898.63,2185.31 ccw(c3900.13,2186.82) 3900.13,2184.69 U2.9@3906.44,2184.69 3911.86,2184.69 ccw(c3911.86,2188.95) 3914.87,2185.93 3914.87,2186.19 3916.45,2187.76 cw(c3920.25,2183.96) 3920.25,2189.34 3956.18,2189.34 ccw(c3956.18,2281.46) 4021.32,2216.32 4042.31,2237.31 cw(c4113.02,2166.6) 4113.02,2266.6 4242.21,2266.6 cw(c4242.21,2262.01) 4245.45,2265.26 ccw(c4248.69,2268.5) 4248.69,2263.91 J15.10@4256.64,2263.91
  L06-BOT w5.38: v1(3020,2069) ccw(c3020,2075.94) 3024.91,2071.03 3025.53,2071.66 cw(c3031.94,2065.24) 3031.94,2074.31 3149.46,2074.31 cw(c3149.46,2010.98) 3194.24,2055.76 cw(c3123.53,1985.05) 3223.53,1985.05 3223.53,1920.1 cw(c3171.44,1920.1) 3208.27,1883.27 cw(c3181.68,1909.86) 3181.68,1872.26 3171.68,1872.26 cw(c3171.68,1888.54) 3160.16,1877.03 cw(c3168.08,1884.94) 3156.88,1884.94 ccw(c3149.94,1884.94) v1(3154.85,1889.85)
ETH_PAIR0_P: J15.12 U2.1 U2.10 U4.2 | length 2592.3
  L01-TOP w5.38: U4.2@2488.86,1666.42 2490.49,1666.42 ccw(c2490.49,1674.36) 2496.11,1668.74 cw(c2501.72,1663.13) 2501.72,1671.07 2595.27,1671.07 ccw(c2595.27,1781.45) 2673.32,1703.4 2859.13,1889.2 3130.01,1889.2 cw(c3130.01,1881.25) 3135.64,1886.87 cw(c3130.01,1881.25) 3137.97,1881.25 3137.97,1879.91 ccw(c3144.91,1879.91) v1(3140,1875) ; v1(3020,2090) cw(c3020,2083.06) 3024.91,2087.97 3025.53,2087.34 ccw(c3031.94,2093.76) 3031.94,2084.69 3065.11,2084.69 ccw(c3065.11,2119.89) 3090,2095 3112.28,2117.28 ccw(c3094.57,2135) 3119.62,2135 3119.62,2144.64 cw(c3215.36,2144.64) 3147.66,2212.34 3148.37,2213.05 cw(c3226.42,2135) 3226.42,2245.38 3318.73,2245.38 cw(c3318.73,2158.73) 3380,2220 ccw(c3428.97,2268.97) 3428.97,2199.72 3857.52,2199.72 ccw(c3857.52,2210.47) 3865.13,2202.87 3865.13,2203.12 3865.75,2203.75 cw(c3867.26,2202.24) 3867.26,2204.37 U2.1@3873.56,2204.37 3878.98,2204.37 cw(c3878.98,2200.11) 3882,2203.12 3882,2202.87 3883.57,2201.29 ccw(c3887.37,2205.09) 3887.37,2199.72 3890.4,2199.72 ccw(c3890.4,2210.47) 3898,2202.87 3898,2203.12 3898.63,2203.75 cw(c3900.13,2202.24) 3900.13,2204.37 U2.10@3906.44,2204.37 3911.86,2204.37 cw(c3911.86,2200.11) 3914.87,2203.12 3914.87,2202.87 3916.45,2201.29 ccw(c3920.25,2205.09) 3920.25,2199.72 3954.03,2199.72 ccw(c3954.03,2286.65) 4015.5,2225.18 4034.97,2244.65 cw(c4113.02,2166.6) 4113.02,2276.98 4242.21,2276.98 ccw(c4242.21,2281.56) 4245.45,2278.32 cw(c4248.69,2275.08) 4248.69,2279.66 J15.12@4256.64,2279.66
  L06-BOT w5.38: v1(3020,2090) cw(c3020,2083.06) 3024.91,2087.97 3025.53,2087.34 ccw(c3031.94,2093.76) 3031.94,2084.69 3155.45,2084.69 cw(c3155.45,2025.45) 3197.34,2067.34 3201.58,2063.1 cw(c3123.53,1985.05) 3233.9,1985.05 3233.9,1910.58 cw(c3194.42,1910.58) 3222.34,1882.66 3215.61,1875.93 cw(c3181.68,1909.86) 3181.68,1861.88 3171.68,1861.88 cw(c3171.68,1888.54) 3152.82,1869.69 ccw(c3144.91,1861.77) 3144.91,1872.97 cw(c3144.91,1879.91) v1(3140,1875)
ETH_PAIR1_N: J15.6 U2.4 U2.7 U4.6 | length 1960.4
  L01-TOP w5.38: U4.6@2488.86,1745.16 2490.49,1745.16 cw(c2490.49,1737.21) 2496.11,1742.83 ccw(c2501.72,1748.45) 2501.72,1740.5 2612.73,1740.5 ccw(c2612.73,1793.85) 2650.45,1756.13 2851.4,1957.07 cw(c2908.41,1900.05) 2908.41,1980.69 2938.06,1980.69 ccw(c2938.06,1989.76) 2944.47,1983.34 2945.09,1983.97 cw(c2950,1979.06) v1(2950,1986) ; v1(3085,2035) cw(c3085,2028.06) 3089.91,2032.97 3090.53,2032.34 ccw(c3096.94,2038.76) 3096.94,2029.69 3104.1,2029.69 ccw(c3104.1,2056.04) 3122.73,2037.41 3193.66,2108.33 cw(c3271.7,2030.28) 3271.7,2140.66 3857.52,2140.66 ccw(c3857.52,2151.42) 3865.13,2143.81 3865.13,2144.07 3865.75,2144.69 cw(c3867.26,2143.18) 3867.26,2145.31 U2.4@3873.56,2145.31 3878.98,2145.31 cw(c3878.98,2141.05) 3882,2144.07 3882,2143.81 3883.57,2142.24 ccw(c3887.37,2146.04) 3887.37,2140.66 3890.4,2140.66 ccw(c3890.4,2151.42) 3898,2143.81 3898,2144.07 3898.63,2144.69 cw(c3900.13,2143.18) 3900.13,2145.31 U2.7@3906.44,2145.31 ccw(c3909.45,2148.33) 3909.45,2144.07 3917.7,2144.07 cw(c3917.7,2132.62) 3925.79,2140.72 4009.62,2140.72 ccw(c4009.62,2240.72) 4080.33,2170 4112.66,2202.34 cw(c4178.8,2136.2) 4178.8,2229.73 4242.21,2229.73 ccw(c4242.21,2234.32) 4245.45,2231.07 cw(c4248.69,2227.83) 4248.69,2232.42 J15.6@4256.64,2232.42
  L06-BOT w5.38: v1(2950,1986) cw(c2950,1979.06) 2954.91,1983.97 ccw(c2962.82,1991.88) 2962.82,1980.69 ccw(c2962.82,2002.83) 2978.48,1987.17 3001.26,2009.95 cw(c3048.9,1962.31) 3048.9,2029.69 3073.06,2029.69 ccw(c3073.06,2038.76) 3079.47,2032.34 3080.09,2032.97 cw(c3085,2028.06) v1(3085,2035)
ETH_PAIR1_P: J15.4 U2.5 U2.6 U4.5 | length 1960.2
  L01-TOP w5.38: U4.5@2488.86,1725.47 2490.49,1725.47 ccw(c2490.49,1733.42) 2496.11,1727.8 cw(c2501.72,1722.18) 2501.72,1730.13 2612.73,1730.13 ccw(c2612.73,1793.85) 2657.79,1748.79 2857.21,1948.21 cw(c2910.56,1894.86) 2910.56,1970.31 2938.06,1970.31 cw(c2938.06,1961.24) 2944.47,1967.66 2945.09,1967.03 ccw(c2950,1971.94) v1(2950,1965) ; v1(3085,2014) ccw(c3085,2020.94) 3089.91,2016.03 3090.53,2016.66 cw(c3096.94,2010.24) 3096.94,2019.31 3106.25,2019.31 ccw(c3106.25,2050.85) 3128.55,2028.55 3200.99,2100.99 cw(c3271.7,2030.28) 3271.7,2130.28 3857.52,2130.28 cw(c3857.52,2119.53) 3865.13,2127.13 3865.13,2126.88 3865.75,2126.25 ccw(c3867.26,2127.76) 3867.26,2125.63 U2.5@3873.56,2125.63 3878.98,2125.63 ccw(c3878.98,2129.89) 3882,2126.88 3882,2127.13 3883.57,2128.71 cw(c3887.37,2124.91) 3887.37,2130.28 3890.4,2130.28 cw(c3890.4,2119.53) 3898,2127.13 3898,2126.88 3898.63,2126.25 ccw(c3900.13,2127.76) 3900.13,2125.63 U2.6@3906.44,2125.63 cw(c3909.45,2122.62) 3909.45,2126.88 3917.44,2126.88 ccw(c3917.44,2138.69) 3925.79,2130.34 4009.62,2130.34 ccw(c4009.62,2240.72) 4087.67,2162.67 4120,2195 cw(c4178.8,2136.2) 4178.8,2219.35 4242.21,2219.35 cw(c4242.21,2214.77) 4245.45,2218.01 ccw(c4248.69,2221.25) 4248.69,2216.67 J15.4@4256.64,2216.67
  L06-BOT w5.38: v1(2950,1965) ccw(c2950,1971.94) 2954.91,1967.03 cw(c2962.82,1959.12) 2962.82,1970.31 ccw(c2962.82,2002.83) 2985.82,1979.84 3007.07,2001.09 cw(c3051.05,1957.12) 3051.05,2019.31 3073.06,2019.31 cw(c3073.06,2010.24) 3079.47,2016.66 3080.09,2016.03 ccw(c3085,2020.94) v1(3085,2014)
